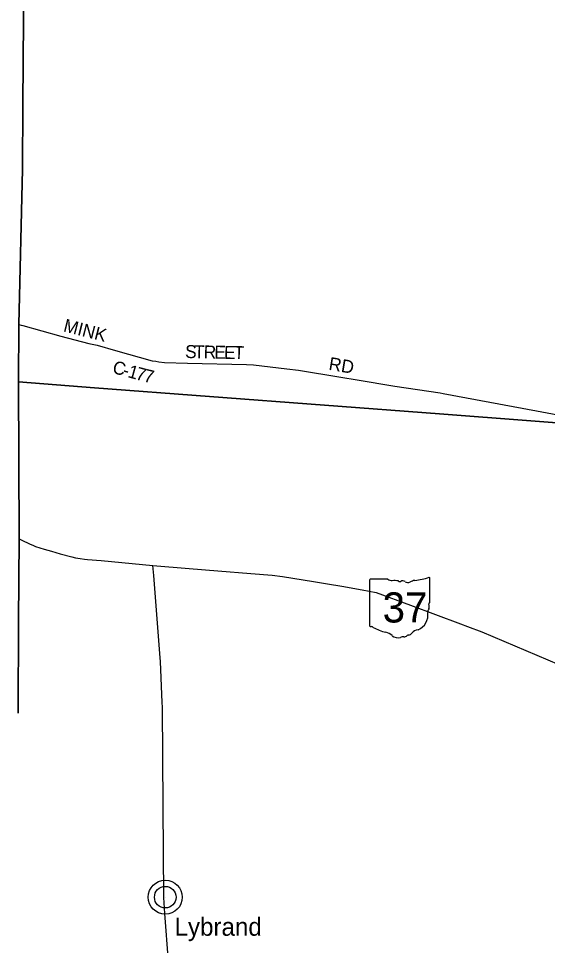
# Model space of a CAD drawing. Extents: x 1674899 to 2057726, y 653888 to 988278.
# Drawn here: x 1759512 to 1771738, y 843541 to 864966 of the extents above; entities that cross this region are included whole.
import ezdxf

# ---------------------------------------------------------------- set-up
doc = ezdxf.new("R2010")
doc.units = 0
for name, color, linetype in [('GM_X_Adjacent_County', 7, 'Continuous'), ('GM_X_County', 7, 'Continuous'), ('GM_X_County_Road', 7, 'Continuous'), ('GM_X_County_Road_Text', 7, 'Continuous'), ('GM_X_State_Location', 7, 'Continuous'), ('GM_X_State_Route', 7, 'Continuous'), ('GM_X_State_Shield', 7, 'Continuous'), ('GM_X_Township', 7, 'Continuous'), ('GM_X_Unincorporated', 7, 'Continuous'), ('GM_X_Unincorporated_Location', 7, 'Continuous'), ('GM_X_Unincorporated_Text', 7, 'Continuous')]:
    doc.layers.add(name, color=color, linetype=linetype)

msp = doc.modelspace()

# ---------------------------------------------------------------- linework, layer by layer
at = {"layer": 'GM_X_Adjacent_County'}
msp.add_lwpolyline([(1759631, 865937), (1759615, 862978), (1759604, 861482), (1759518, 857896), (1759514, 856565), (1759526, 852942), (1759514, 851039), (1759505, 848913)], dxfattribs=at)
at = {"layer": 'GM_X_County'}
msp.add_lwpolyline([(1759505, 848913), (1759514, 851039), (1759526, 852942), (1759514, 856565), (1759518, 857896), (1759604, 861482), (1759615, 862978), (1759631, 865937)], dxfattribs=at)
at = {"layer": 'GM_X_County_Road'}
for points in [[(1759518, 857896), (1759574, 857878), (1759613, 857869), (1760488, 857624), (1761137, 857456), (1761330, 857415)], [(1761330, 857415), (1761757, 857293), (1762604, 857057), (1762687, 857045), (1762755, 857030), (1762889, 857019), (1763416, 856999), (1764783, 856969), (1764940, 856958), (1765711, 856869), (1765986, 856836), (1766962, 856678), (1767342, 856615), (1768207, 856468), (1769260, 856311), (1769327, 856301), (1771485, 855899), (1771485, 855899)], [(1771485, 855899), (1772805, 855652), (1772899, 855634), (1774513, 855940), (1774515, 855940)], [(1764156, 832620), (1763784, 836032), (1763776, 836097), (1763123, 841759), (1763037, 842583), (1762977, 843169), (1762897, 844278), (1762874, 844646), (1762856, 846750), (1762837, 849052), (1762835, 849154), (1762790, 850103), (1762786, 850187), (1762639, 852096), (1762618, 852326)]]:
    msp.add_lwpolyline(points, dxfattribs=at)
at = {"layer": 'GM_X_State_Route'}
msp.add_lwpolyline([(1759526, 852942), (1759591, 852908), (1759768, 852824), (1759855, 852784), (1759903, 852765), (1760002, 852730), (1760102, 852701), (1760277, 852652), (1760476, 852596), (1760744, 852525), (1760828, 852502), (1760935, 852482), (1761034, 852468), (1761108, 852461), (1761421, 852437), (1762618, 852326), (1763459, 852257), (1764120, 852204), (1764882, 852142), (1765375, 852101), (1765612, 852072), (1766327, 851954), (1766657, 851900), (1766981, 851843), (1767455, 851763), (1767775, 851700), (1768574, 851406), (1769730, 850976), (1769888, 850917), (1770221, 850789), (1771999, 850032)], dxfattribs=at)
at = {"layer": 'GM_X_State_Shield'}
for p, q in [((1767627, 851988), (1767627, 850931)), ((1768049, 852006), (1767641, 852006)), ((1769020, 851480), (1769020, 852032)), ((1769019, 851480), (1769020, 851480))]:
    msp.add_line(p, q, dxfattribs=at)
for centre, radius, start, end in [((1767643, 851990), 16.1, 98.1301, 188.1301), ((1768146, 852129), 156, 231.6195, 271.1119), ((1768198, 851413), 562, 80.4867, 94.9883), ((1768325, 851996), 45.1, 219.7921, 297.1024), ((1768392, 851874), 93.8, 54.4667, 119.1411), ((1768513, 852041), 113, 233.8562, 294.8282), ((1768712, 851684), 297, 97.3462, 120.7689), ((1768524, 853447), 1476, 275.8445, 288.9065), ((1769004, 852035), 15.5, 351.8621, 97.738), ((1769016, 851439), 24, 107.944, 210.337), ((1769003, 851478), 16.6, 289.6038, 7.7341), ((1768606, 851178), 369, 292.3089, 8.9858), ((1769075, 851248), 105, 136.8065, 186.9296), ((1768863, 851369), 144, 340.033, 23.6496), ((1767644, 850929), 16.3, 171.9584, 258.3066), ((1767646, 851037), 124, 267.339, 280.6039), ((1767671, 850870), 44.8, 29.7484, 93.2717), ((1768237, 851820), 1066, 240.4129, 257.1985), ((1768762, 850635), 202, 94.4031, 142.5768), ((1767919, 850457), 334, 47.1842, 75.836), ((1768280, 850865), 212, 230.7004, 286.2918), ((1768402, 850500), 174, 85.6951, 111.2099), ((1768417, 850786), 113, 268.777, 315.5493), ((1768519, 850684), 31.8, 65.7517, 132.6484), ((1768506, 850829), 119, 282.8732, 323.2771)]:
    msp.add_arc(centre, radius, start, end, dxfattribs=at)
at = {"layer": 'GM_X_Township'}
for points in [[(1775377, 855361), (1769242, 855826), (1761265, 856432), (1759514, 856565), (1759518, 857896), (1759604, 861482), (1759615, 862978), (1759631, 865937)], [(1759505, 848913), (1759514, 851039), (1759526, 852942), (1759514, 856565), (1761265, 856432), (1769242, 855826), (1775377, 855361)]]:
    msp.add_lwpolyline(points, dxfattribs=at)
at = {"layer": 'GM_X_Unincorporated'}
for radius in [393, 249]:
    msp.add_circle((1762903, 844657), radius, dxfattribs=at)
at = {"layer": 'GM_X_Unincorporated_Location'}
msp.add_line((1762903, 844657), (1762903, 844657), dxfattribs=at)

# ---------------------------------------------------------------- texts
at = {"layer": 'GM_X_County_Road_Text'}
for s, rotation, p in [('MINK', 345.7184, (1760531, 857739)), ('S', 358.0991, (1763358, 857122)), ('T', 358.8413, (1763564, 857115)), ('R', 358.8589, (1763789, 857111)), ('E', 358.8586, (1764035, 857106)), ('E', 358.8616, (1764259, 857101)), ('T', 358.8599, (1764484, 857097)), ('C', 344.3505, (1761663, 856780)), ('RD', 350.5372, (1766667, 856848)), ('-', 344.3783, (1761900, 856713)), ('1', 344.4931, (1762020, 856680)), ('7', 344.9437, (1762200, 856630)), ('7', 346.4859, (1762387, 856580))]:
    msp.add_text(s, height=300, rotation=rotation, dxfattribs=at).set_placement(p)
at = {"layer": 'GM_X_State_Location'}
msp.add_text('37', height=1, rotation=0, dxfattribs=at).set_placement((1768056, 851317))
for s in ['s', 'r']:
    msp.add_text(s, height=1, dxfattribs=at).set_placement((1768308, 851390))
at = {"layer": 'GM_X_State_Shield'}
msp.add_text('37', height=696.1, dxfattribs=at).set_placement((1767928, 851006))
at = {"layer": 'GM_X_Unincorporated_Text'}
msp.add_text('Lybrand', height=417, rotation=0, dxfattribs=at).set_placement((1763119, 843765))

doc.saveas('drawing.dxf')
